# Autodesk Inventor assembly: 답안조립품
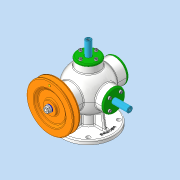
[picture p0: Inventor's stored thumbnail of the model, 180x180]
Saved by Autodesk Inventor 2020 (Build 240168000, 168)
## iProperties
Created: 2021-10
Part Number: 답안조립품
Document SubType Name: Assembly
Designer: user
Mass: 3778.22 g
Surface Area: 2410.89 cm^2
Volume: 904.615 cm^3
Density: 4.17661 g/cm^3
Author: user
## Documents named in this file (17)
- C:\Users\user\Desktop\611007V1008\답안조립품.iam
- C:\Users\user\Desktop\611007V1008\V-벨트풀리.ipt
- C:\Users\user\Desktop\611007V1008\가변스프링.ipt
- C:\Users\user\Desktop\611007V1008\너트 M8x1.ipt
- C:\Users\user\Desktop\611007V1008\뒤커버.ipt
- C:\Users\user\Desktop\611007V1008\베어링 6202.ipt
- C:\Users\user\Desktop\611007V1008\본체.ipt
- C:\Users\user\Desktop\611007V1008\본체커버.ipt
- C:\Users\user\Desktop\611007V1008\볼트 M4.ipt
- C:\Users\user\Desktop\611007V1008\슬라이드 커버.ipt
- C:\Users\user\Desktop\611007V1008\슬라이드.ipt
- C:\Users\user\Desktop\611007V1008\앞커버.ipt
- C:\Users\user\Desktop\611007V1008\오일 실.ipt
- C:\Users\user\Desktop\611007V1008\와셔 8x17.ipt
- C:\Users\user\Desktop\611007V1008\축.ipt
- C:\Users\user\Desktop\611007V1008\키 4x4.ipt
- C:\Users\user\Desktop\611007V1008\가변스프링2.ipt
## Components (3 placed, 3 different names)
1. V-벨트풀리:1
2. 가변스프링:1
3. 가변스프링2:1
